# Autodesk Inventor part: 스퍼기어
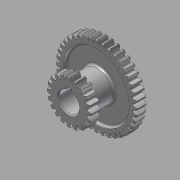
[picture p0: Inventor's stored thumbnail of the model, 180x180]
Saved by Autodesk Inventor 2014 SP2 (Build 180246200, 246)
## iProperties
Created: 2015-09
Part Number: 스퍼기어
Material: 강철, 연강
Document SubType Name: Modeling
Designer: mduedu
Density: 7.86 g/cm^3
Mass: 345.726 g
Surface Area: 225.641 cm^2
Volume: 43.9855 cm^3
Appearance: 강철
Author: mduedu
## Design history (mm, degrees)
sketch "스케치1"
  geometry: C1 r 38 at (0, 0); C2 r 40 at (0, 0); C3 r 35.5 at (0, 0); 1 further point
  constraints: 3 centre point, 3 coincident
  dimensions: "d0" = 76 diameter of C1; "d2" = 2 radial gap between concentric circles of C2 C1; "d3" = 71 diameter of C3 (computed from d0)
extrude "돌출1" new body sketch "스케치1" stored distance "d4" = 10; taper "d5" = 0 deg
sketch "스케치2"
  geometry: L1 (0, 35.5)-(0, -35.5); L2 (0, 0)-(40, 0); L3 (0, 0.57)-(39.996, 0.57); L4 (0, 1.57)-(39.969, 1.57); L5 (0, 2.07)-(39.946, 2.07); A1 r 35.5 centre (0, 0) between (0, 35.5) and (0, -35.5) reference; A2 r 40 centre (0, 0) between (40, 0) and (39.946, 2.07) reference; A3 r 9.234 centre (34.93, -7.149) between (39.996, 0.57) and (35.44, 2.07); A4 r 9.234 centre (34.93, 7.149) between (35.44, -2.07) and (39.996, -0.57); A5 r 40 centre (0, 0) between (39.996, -0.57) and (39.996, 0.57); A6 r 35.5 centre (0, 0) between (35.44, -2.07) and (35.44, 2.07); 4 further points
  constraints: 16 point on circle, 10 end point, 6 point on line, 4 centre point, 3 coincident, 3 parallel, 3 symmetric about line, 2 midpoint, 1 perpendicular, 1 vertical, 3 other
  dimensions: "d6" = 0.5 distance between parallel lines of L4 L5; "d8" = 1 distance between parallel lines of L3 L4; "d9" = 1.57 distance between parallel lines of L2 L4
extrude "돌출2" join sketch "스케치2" distance "d10" = 5; taper "d12" = 0 deg; dims "d11" = 5, "d13" = 0
fillet "모깎기1" dims "d17" = 0.5
chamfer "모따기1" distance "d21" = 1; stored, may be unused: second distance "d22" = 2, angle "d23" = 45 deg
sketch "스케치3"
  geometry: C1 r 32.5 at (0, 0); C2 r 15 at (0, 0); 1 further point
  constraints: 2 centre point, 2 coincident
  dimensions: "d27" = 65 diameter of C1; "d28" = 30 diameter of C2
extrude "돌출3" cut sketch "스케치3" distance "d29" = 3; taper "d30" = 0 deg
fillet "모깎기2" dims "d31" = 2
node "작업 평면2"
  node "작업 평면1"
sketch "스케치4"
  geometry: C1 r 15 at (0, 0) reference; 1 further point
extrude "돌출4" join sketch "스케치4" stored distance "d34" = 3; taper "d35" = 0 deg
sketch "스케치5"
  geometry: C1 r 17.5 at (0, 0); C2 r 20 at (0, 0); C3 r 22 at (0, 0); 1 further point
  constraints: 3 centre point, 3 coincident
  dimensions: "d36" = 40 diameter of C2; "d38" = 2 radial gap between concentric circles of C2 C3; "d39" = 35 diameter of C1 (= d36 - 2.5 x d38)
extrude "돌출6" join sketch "스케치5" distance "d46" = 10; taper "d47" = 0 deg
sketch "스케치6"
  geometry: L1 (0, 0)-(0, 22); L2 (-17.5, 0)-(17.5, 0); L3 (-0.57, 0)-(-0.57, 21.993); L4 (-1.57, 0)-(-1.57, 21.944); L5 (-2.07, 0)-(-2.07, 21.902); A1 r 22 centre (0, 0) between (0, 22) and (-0.57, 21.993) reference; A2 r 17.5 centre (0, 0) between (-17.5, 0) and (17.5, 0) reference; A3 r 9.431 centre (7.348, 16.868) between (-0.57, 21.993) and (-2.07, 17.377); A4 r 9.431 centre (-7.348, 16.868) between (2.07, 17.377) and (0.57, 21.993); A5 r 17.5 centre (0, 0) between (2.07, 17.377) and (-2.07, 17.377); A6 r 22 centre (0, 0) between (0.57, 21.993) and (-0.57, 21.993); 4 further points
  constraints: 16 point on circle, 10 end point, 5 point on line, 4 centre point, 3 coincident, 3 symmetric about line, 2 parallel, 2 perpendicular, 1 midpoint, 1 vertical, 3 other
  dimensions: "d40" = 0.5 distance between parallel lines of L4 L5; "d42" = 1 distance between parallel lines of L3 L4; "d43" = 1.57 distance between parallel lines of L1 L4
extrude "돌출5" join sketch "스케치6" distance "d44" = 10; taper "d45" = 0 deg
fillet "모깎기3" dims "d48" = 0.5
chamfer "모따기2" distance "d49" = 1; stored, may be unused: second distance "d50" = 2, angle "d51" = 45 deg
sketch "스케치7"
  geometry: C1 r 10 at (0, 0); 1 further point
  constraints: 1 centre point, 1 coincident
  dimensions: "d55" = 20 diameter of C1
extrude "돌출7" cut sketch "스케치7" stored distance "d56" = 10; taper "d57" = 0 deg
sketch "스케치8"
  geometry: L1 (-9.539, -3)-(-12.8, -3); L2 (-12.8, -3)-(-12.8, 3); L3 (-12.8, 3)-(-9.539, 3); L4 (-9.539, 3)-(-9.539, -3); A1 r 10 centre (0, 0) between (-9.539, -3) and (-9.539, 3) reference; 2 further points
  constraints: 8 end point, 3 point on circle, 2 parallel, 1 horizontal, 1 horizontal alignment, 1 perpendicular
  dimensions: "d58" = 6 distance of L1.end L2.end; "d60" = 22.8 distance from line of point (10, 0) L2
extrude "돌출8" cut sketch "스케치8" stored distance "d61" = 10; taper "d62" = 0 deg
chamfer "모따기3" distance "d63" = 1; stored, may be unused: second distance "d64" = 2, angle "d65" = 45 deg
fillet "모깎기4" dims "d66" = 2
node "솔리드1"
pattern_circular "원형 패턴3" dims "d25" = 360 deg
mirror "대칭1"
pattern_circular "원형 패턴4" dims "d53" = 360 deg
other parameters: "d32" = 5, "d33" = 42
